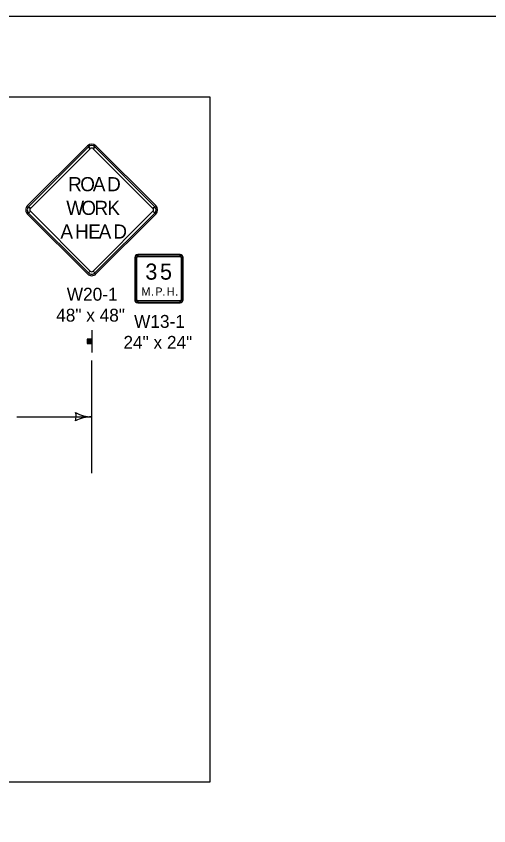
# Model space of a CAD drawing. Extents: x -2134934 to -2122394, y -2139046 to -2137036.
# Drawn here: x -2124549 to -2123962, y -2138041 to -2137036 of the extents above; entities that cross this region are included whole.
import ezdxf

# ---------------------------------------------------------------- set-up
doc = ezdxf.new("R2010")
doc.units = 0
for name, color, linetype in [('Barrier', 7, 'Continuous'), ('BridgeSuperStructureExisting', 7, 'Continuous'), ('Default', 7, 'Continuous')]:
    doc.layers.add(name, color=color, linetype=linetype)

msp = doc.modelspace()

# ---------------------------------------------------------------- linework, layer by layer
at = {"layer": 'Barrier'}
for p, q in [((-2124460.1, -2137196.8), (-2124534.4, -2137271.1)), ((-2124458.8, -2137198.1), (-2124456.6, -2137200.4)), ((-2124453.1, -2137200.4), (-2124450.9, -2137198.1)), ((-2124375.3, -2137271.1), (-2124449.5, -2137196.8)), ((-2124530.9, -2137274.6), (-2124533.1, -2137272.4)), ((-2124533.1, -2137280.3), (-2124530.9, -2137278.1)), ((-2124376.6, -2137272.4), (-2124378.8, -2137274.6)), ((-2124378.8, -2137278.1), (-2124376.6, -2137280.3)), ((-2124534.4, -2137281.7), (-2124460.1, -2137355.9)), ((-2124449.5, -2137355.9), (-2124375.3, -2137281.7)), ((-2124401.3, -2137335.5), (-2124401.3, -2137388)), ((-2124400.4, -2137335.5), (-2124398.8, -2137335.5)), ((-2124345.1, -2137331.8), (-2124397.6, -2137331.8)), ((-2124397.6, -2137334.3), (-2124397.6, -2137332.7)), ((-2124345.1, -2137332.7), (-2124345.1, -2137334.3)), ((-2124343.8, -2137335.5), (-2124342.3, -2137335.5)), ((-2124341.3, -2137388), (-2124341.3, -2137335.5)), ((-2124456.6, -2137352.4), (-2124458.8, -2137354.6)), ((-2124450.9, -2137354.6), (-2124453.1, -2137352.4)), ((-2124398.8, -2137388), (-2124400.4, -2137388)), ((-2124397.6, -2137390.8), (-2124397.6, -2137389.3)), ((-2124345.1, -2137389.3), (-2124345.1, -2137390.8)), ((-2124342.3, -2137388), (-2124343.8, -2137388)), ((-2124397.6, -2137391.8), (-2124345.1, -2137391.8))]:
    msp.add_line(p, q, dxfattribs=at)
for points in [[(-2125429.5, -2137135.9), (-2124308.2, -2137135.9), (-2124308.2, -2137986.6), (-2125429.5, -2137986.6)], [(-2124458.8, -2137198.1), (-2124533.1, -2137272.4), (-2124530.9, -2137274.6), (-2124456.6, -2137200.4), (-2124458.8, -2137198.1)], [(-2124376.6, -2137272.4), (-2124450.9, -2137198.1), (-2124453.1, -2137200.4), (-2124378.8, -2137274.6), (-2124376.6, -2137272.4)], [(-2124533.1, -2137280.3), (-2124458.8, -2137354.6), (-2124456.6, -2137352.4), (-2124530.9, -2137278.1), (-2124533.1, -2137280.3)], [(-2124450.9, -2137354.6), (-2124376.6, -2137280.3), (-2124378.8, -2137278.1), (-2124453.1, -2137352.4), (-2124450.9, -2137354.6)], [(-2124400.4, -2137335.5), (-2124400.4, -2137388), (-2124398.8, -2137388), (-2124398.8, -2137335.5), (-2124400.4, -2137335.5)], [(-2124345.1, -2137332.7), (-2124397.6, -2137332.7), (-2124397.6, -2137334.3), (-2124345.1, -2137334.3), (-2124345.1, -2137332.7)], [(-2124342.3, -2137388), (-2124342.3, -2137335.5), (-2124343.8, -2137335.5), (-2124343.8, -2137388), (-2124342.3, -2137388)], [(-2124397.6, -2137390.8), (-2124345.1, -2137390.8), (-2124345.1, -2137389.3), (-2124397.6, -2137389.3), (-2124397.6, -2137390.8)]]:
    msp.add_lwpolyline(points, close=True, dxfattribs=at)
for centre, radius, start, end in [((-2124454.8, -2137202.1), 7.5, 45, 134.9997), ((-2124454.8, -2137202.1), 5.62, 45, 134.9997), ((-2124454.8, -2137202.1), 2.5, 45, 134.9997), ((-2124529.1, -2137276.4), 7.5, 134.9997, 225), ((-2124529.1, -2137276.4), 5.62, 134.9997, 225), ((-2124529.1, -2137276.4), 2.5, 134.9997, 225), ((-2124380.6, -2137276.4), 2.5, 315.0002, 44.9998), ((-2124380.6, -2137276.4), 5.62, 315.0002, 44.9998), ((-2124380.6, -2137276.4), 7.5, 315.0002, 44.9998), ((-2124397.6, -2137335.5), 3.75, 90.0002, 179.9998), ((-2124397.6, -2137335.5), 2.81, 90.0002, 179.9998), ((-2124397.6, -2137335.5), 1.25, 90.0002, 179.9998), ((-2124345.1, -2137335.5), 3.75, 0, 90.0002), ((-2124345.1, -2137335.5), 2.81, 0, 90.0002), ((-2124345.1, -2137335.5), 1.25, 0, 90.0002), ((-2124454.8, -2137350.6), 7.5, 225, 315.0002), ((-2124454.8, -2137350.6), 5.62, 225, 315.0002), ((-2124454.8, -2137350.6), 2.5, 225, 315.0002), ((-2124397.6, -2137388), 3.75, 179.9998, 270.0001), ((-2124397.6, -2137388), 2.81, 179.9998, 270.0001), ((-2124397.6, -2137388), 1.25, 179.9998, 270.0001), ((-2124345.1, -2137388), 3.75, 270.0001, 0.0003), ((-2124345.1, -2137388), 2.81, 270.0001, 0.0003), ((-2124345.1, -2137388), 1.25, 270.0001, 0.0003)]:
    msp.add_arc(centre, radius, start, end, dxfattribs=at)
at = {"layer": 'BridgeSuperStructureExisting'}
for p, q in [((-2124454.8, -2137425.9), (-2124454.8, -2137453.4)), ((-2124460.2, -2137436.8), (-2124460.2, -2137442.4)), ((-2124459.8, -2137442.4), (-2124459.8, -2137436.8)), ((-2124459.6, -2137436.8), (-2124459.6, -2137442.4)), ((-2124459.3, -2137442.4), (-2124459.3, -2137436.8)), ((-2124459.1, -2137436.8), (-2124459.1, -2137442.4)), ((-2124458.7, -2137442.4), (-2124458.6, -2137436.8)), ((-2124458.4, -2137436.8), (-2124458.4, -2137442.4)), ((-2124458, -2137442.4), (-2124458, -2137436.8)), ((-2124457.6, -2137436.8), (-2124457.6, -2137442.4)), ((-2124457.3, -2137442.4), (-2124457.3, -2137436.8)), ((-2124457.1, -2137436.8), (-2124457.1, -2137442.4)), ((-2124456.8, -2137442.4), (-2124456.8, -2137436.8)), ((-2124456.5, -2137436.8), (-2124456.5, -2137442.4)), ((-2124456.3, -2137442.4), (-2124456.3, -2137436.8)), ((-2124456.1, -2137436.8), (-2124456.1, -2137442.4)), ((-2124455.8, -2137442.4), (-2124455.8, -2137436.8)), ((-2124455.5, -2137436.8), (-2124455.5, -2137442.4)), ((-2124455.2, -2137442.4), (-2124455.2, -2137436.8)), ((-2124454.8, -2137603.4), (-2124454.8, -2137463.4)), ((-2124547.6, -2137533.4), (-2124454.8, -2137533.4))]:
    msp.add_line(p, q, dxfattribs=at)
msp.add_lwpolyline([(-2124454.9, -2137442.4), (-2124454.9, -2137436.8), (-2124460.6, -2137436.8), (-2124460.6, -2137442.4)], close=True, dxfattribs=at)
for centre, radius, start, end in [((-2124490.5, -2137532.8), 16.4, 341.2666, 16.7334), ((-2124454.1, -2137490.9), 42.5, 240.9275, 268.9824), ((-2124455.6, -2137575.9), 42.5, 89.0176, 117.0725)]:
    msp.add_arc(centre, radius, start, end, dxfattribs=at)
at = {"layer": 'Default'}
msp.add_lwpolyline([(-2125529.5, -2137035.9), (-2122394.5, -2137035.9), (-2122394.5, -2139045.9), (-2125529.5, -2139045.9)], close=True, dxfattribs=at)

# ---------------------------------------------------------------- texts
at = {"layer": 'Barrier'}
for s, height, p in [('R', 17.5, (-2124484, -2137253.2)), ('O', 17.5, (-2124469, -2137253.2)), ('A', 17.5, (-2124453.4, -2137253.2)), ('D', 17.5, (-2124435.6, -2137253.2)), ('W', 17.5, (-2124486.3, -2137282.6)), ('O', 17.5, (-2124467.7, -2137282.6)), ('R', 17.5, (-2124451.3, -2137282.6)), ('K', 17.5, (-2124435.4, -2137282.6)), ('A', 17.5, (-2124493.6, -2137312)), ('H', 17.5, (-2124475.4, -2137312)), ('E', 17.5, (-2124459.1, -2137312)), ('A', 17.5, (-2124446.1, -2137312)), ('D', 17.5, (-2124427.9, -2137312)), ('3', 20, (-2124388.2, -2137363)), ('5', 20, (-2124370, -2137363)), ('W20-1', 16, (-2124485.7, -2137389.1)), ('M', 10, (-2124393.1, -2137382.7)), ('P', 10, (-2124375.8, -2137382.7)), ('H', 10, (-2124361.7, -2137382.7)), ('.', 10, (-2124381.3, -2137382.7)), ('.', 10, (-2124367.2, -2137382.7)), ('.', 10, (-2124351.2, -2137382.7)), ('48" x 48"', 16, (-2124498.9, -2137415.1)), ('W13-1', 16, (-2124402.2, -2137422.8)), ('24" x 24"', 16, (-2124415.4, -2137448.8))]:
    msp.add_text(s, height=height, dxfattribs=at).set_placement(p)

doc.saveas('drawing.dxf')
